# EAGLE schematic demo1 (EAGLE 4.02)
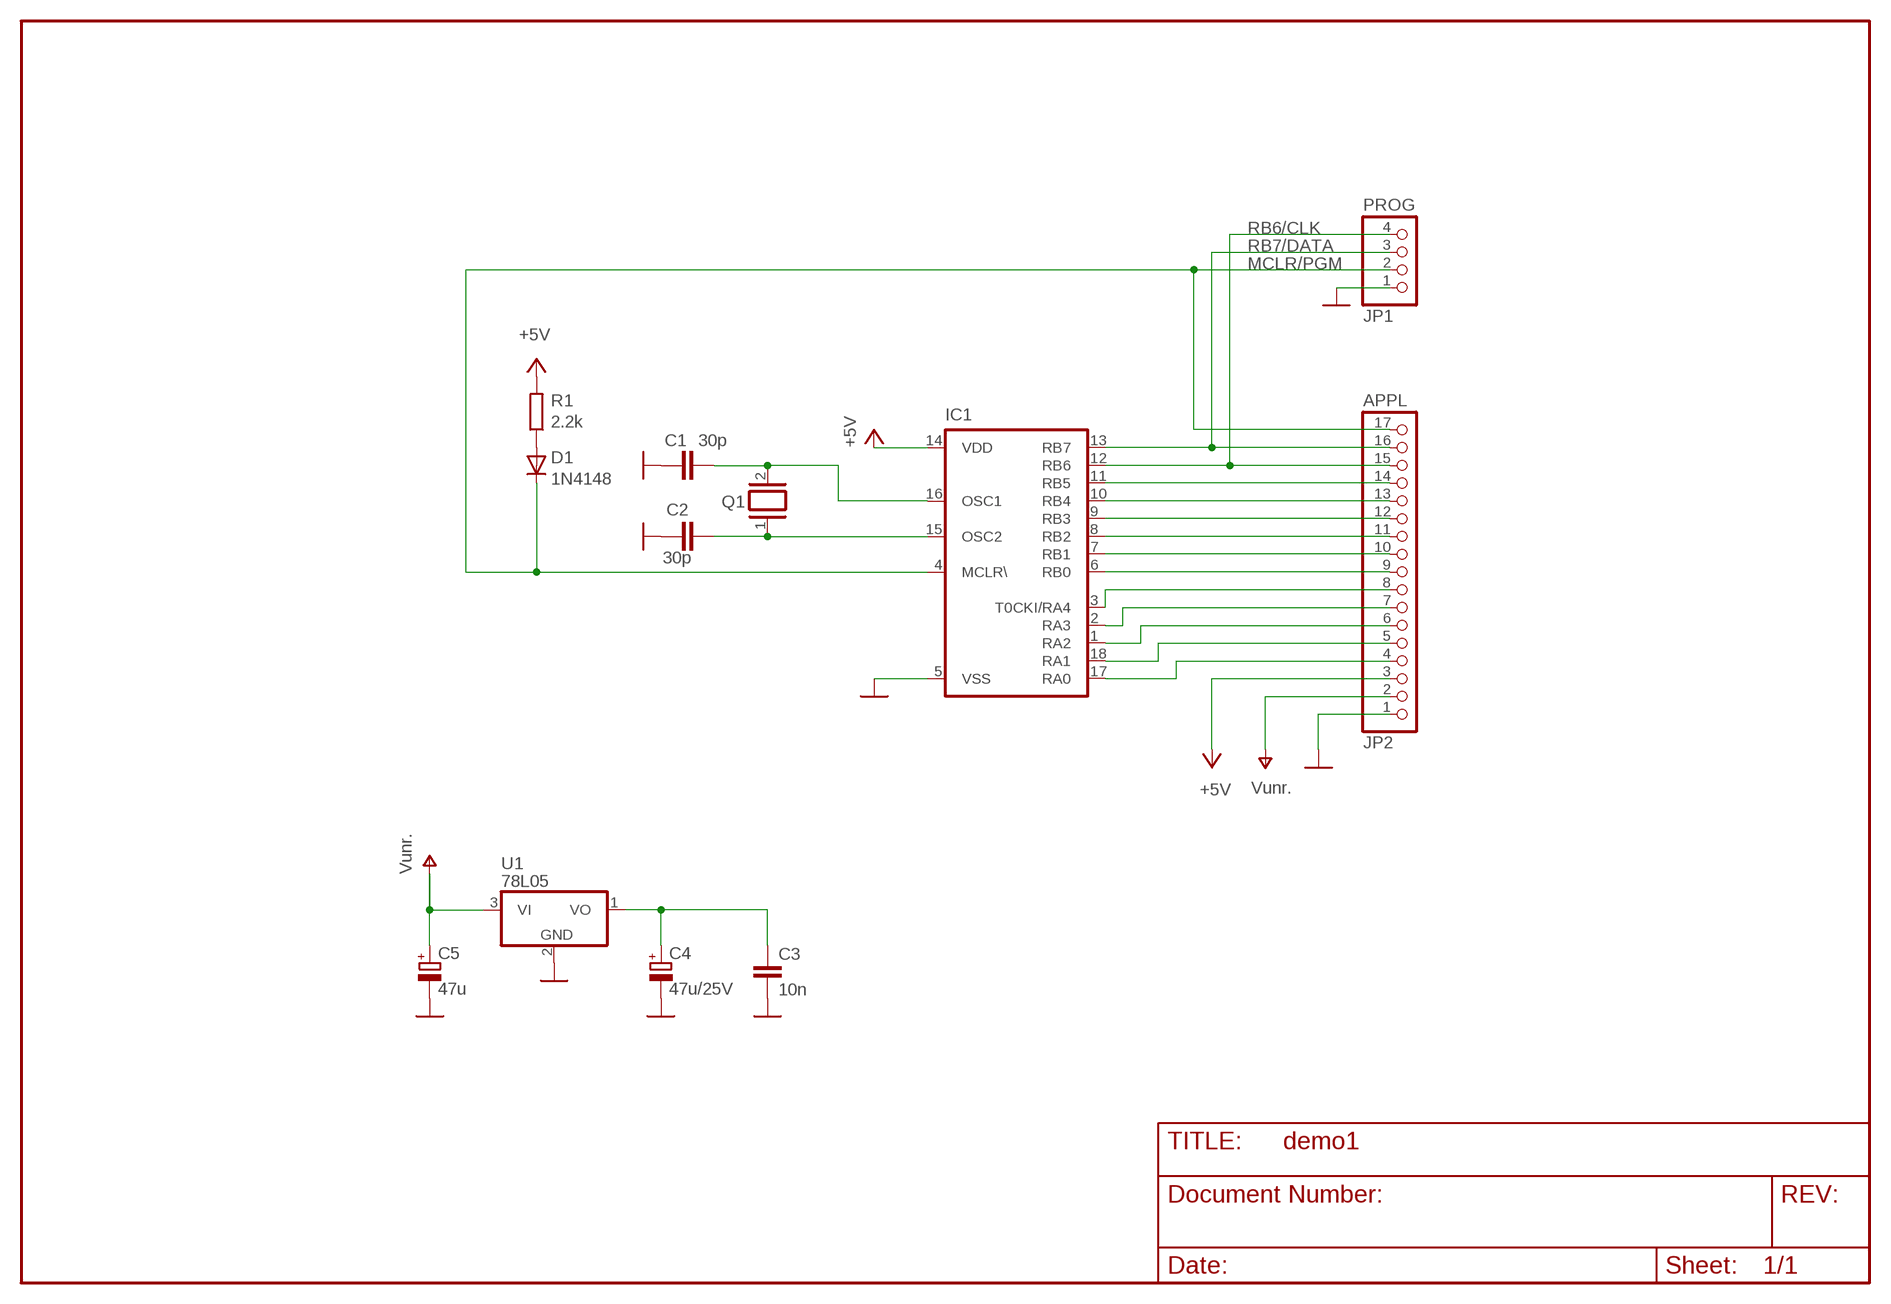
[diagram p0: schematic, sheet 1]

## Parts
C1  30p  C-EUC1206  [C1206]
C2  30p  C-EUC1206  [C1206]
C3  10n  C-EU025-025X050  [C025-025X050]
C4  47u/25V  CPOL-TAP5-45  [TAP5-45]
C5  47u  CPOL-TAP5-45  [TAP5-45]
D1  1N4148  [DO35-10]
IC1  PIC16F84AP  [DIL18]
JP1  PROG  PINHD-1X4  [1X04]
JP2  APPL  PINHD-1X17  [1X17]
Q1  XTAL/S  [QS]
R1  2.2k  R-EU_R1206  [R1206]
U1  78L05  78LXXZ  [TO92]

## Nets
GND [power]: C1.2 C2.2 C3.1 C4.- C5.- IC1.5(VSS) JP1.1 JP2.1 U1.2(GND)
MCLR/PGM: D1.K IC1.4(MCLR\) JP1.2 JP2.17
N$1: C3.2 C4.+ U1.1(VO)
N$2: C1.1 IC1.16(OSC1) Q1.2
N$3: C2.1 IC1.15(OSC2) Q1.1
N$5: D1.A R1.1
RA0: IC1.17(RA0) JP2.4
RA1: IC1.18(RA1) JP2.5
RA2: IC1.1(RA2) JP2.6
RA3: IC1.2(RA3) JP2.7
RA4: IC1.3(T0CKI/RA4) JP2.8
RB0: IC1.6(RB0) JP2.9
RB1: IC1.7(RB1) JP2.10
RB2: IC1.8(RB2) JP2.11
RB3: IC1.9(RB3) JP2.12
RB4: IC1.10(RB4) JP2.13
RB5: IC1.11(RB5) JP2.14
RB6/CLK: IC1.12(RB6) JP1.4 JP2.15
RB7/DATA: IC1.13(RB7) JP1.3 JP2.16
V+ [power]: C5.+ JP2.2 U1.3(VI) ; supply symbol labelled Vunr.
VCC [power]: IC1.14(VDD) JP2.3 R1.2 ; supply symbol labelled +5V

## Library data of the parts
C1-C3 = rcl:C-EU: capacitor EUrop Symbol
C4 C5 = rcl:CPOL-: polarity capacitor (Tantalum, Electrolyt) EUrop Symbol
D1 = diode:1N4148: 1N4148 - High Conductance Fast Diode
IC1 = microchip:PIC16F8*: 8-Bit Microcontroller PIC16F8X Family - CMOS Flash/EEPROM Pin Compatible : PIC16F83, PIC16CR83, PIC16F84A, PIC16CR84 see also PIC16C*
JP1 = PINHEAD:PINHD-1X4
JP2 = PINHEAD:PINHD-1X17
Q1 = special:XTAL/S
R1 = rcl:R-EU_: resistor EUrop Symbol
U1 = linear:78LXXZ: positiv voltage regulator / low power TO92

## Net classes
0 default: width 0.2 mm, drill 0.2 mm, clearance 0.8 mm
1 power: width 0.4 mm, drill 0.2 mm, clearance 0.2 mm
